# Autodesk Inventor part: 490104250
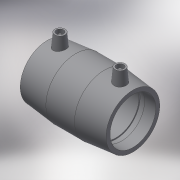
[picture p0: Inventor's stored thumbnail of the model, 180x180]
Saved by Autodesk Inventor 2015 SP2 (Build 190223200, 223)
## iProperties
Created: 2017-06
Part Number: 490104250
Material: Generic
Description: PLASSON COUPLER 250-250
Document SubType Name: Modeling
Designer: KIM
Mass: 5639.55 g
Surface Area: 4908.99 cm^2
Volume: 5639.55 cm^3
Density: 1 g/cm^3
Appearance: Default
Author: KIM
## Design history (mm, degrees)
derived "490104.ipt"
feature "Solid1::490104.ipt"
tag "TaggingFeature1"
body "Solid1"
other parameters: "d0" = 251, "d2" = 311, "d3" = 123, "d4" = 83.66667, "d5" = 279.9, "d6" = 237.5, "d8" = 168 deg, "d10" = 49.2, "d11" = 16.4, "d13" = 251, "d14" = 17.6296, "d15" = 123, "d16" = 123, "d17" = 237.5, "d19" = 3.52592, "d20" = 168 deg, "d22" = 292.34, "d23" = 311, "d24" = 283.5698, "d25" = 135 deg, "d26" = 125.5, "d27" = 135 deg, "d29" = 156, "d30" = 14, "d31" = 87.85, "d34" = 5 deg, "d35" = 15, "d39" = 5 deg, "d41" = 4, "d42" = 14, "d43" = 0, "d45" = 4, "d46" = 14, "d47" = 0, "d48" = 3, "d49" = 0, "d50" = 3, "d51" = 0, "d52" = 35.67, "d53" = 8.9175, "L_" = 251, "L_1" = 123, "D_" = 311, "A_" = 156, "d_2" = 12
